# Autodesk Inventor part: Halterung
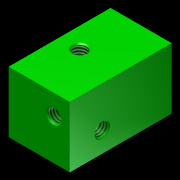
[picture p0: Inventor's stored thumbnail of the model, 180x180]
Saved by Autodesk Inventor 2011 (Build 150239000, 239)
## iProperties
Created: 2012-06
Part Number: Halterung
Document SubType Name: Modeling
Designer: M.Schulte
Density: 1 g/cm^3
Author: M.Schulte
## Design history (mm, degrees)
sketch "Skizze1"
  geometry: L1 (-7.5, -7.5)-(7.5, -7.5); L2 (7.5, -7.5)-(7.5, 7.5); L3 (7.5, 7.5)-(-7.5, 7.5); L4 (-7.5, 7.5)-(-7.5, -7.5); 4 further points
  constraints: 8 end point, 2 midpoint, 2 parallel, 1 horizontal, 1 horizontal alignment, 1 perpendicular, 1 vertical alignment
  dimensions: "d0" = 15 distance of L1.end L2.end; "d1" = 15 distance of L2.end L3.end (= d0); "d4" = 10 vertical distance of L1.end point (3.5, 2.5); "d5" = 4 horizontal distance of L2.end point (3.5, 2.5)
extrude "Extrusion1" new body sketch "Skizze1" distance "d2" = 25; taper "d3" = 0 deg
hole "Hole1" sketch "Skizze1" diameter "d6" = 3.242; stored, may be unused: countersink angle "d10" = 90 deg, drill point angle "d12" = 118 deg; dims "d7" = 15, "d8" = 4, "d9" = 2, "d11" = 18
sketch "Skizze2"
  geometry: 3 further points
  dimensions: "d13" = 12.5 vertical distance of point (0, 0) point (5, -12.5); "d14" = 5 horizontal distance of point (0, 0) point (5, -12.5)
hole "Hole2" sketch "Skizze2" at (5, -12.5) diameter "d15" = 3.242; stored, may be unused: countersink angle "d19" = 90 deg, drill point angle "d21" = 118 deg; dims "d16" = 15, "d17" = 4, "d18" = 2, "d20" = 18
sketch "Skizze3"
  geometry: 3 further points
  dimensions: "d22" = 8 horizontal distance of point (0, 0) point (8, 5); "d23" = 5 vertical distance of point (0, 0) point (8, 5)
hole "Hole3" sketch "Skizze3" at (8, 5) diameter "d24" = 3.242; stored, may be unused: countersink angle "d28" = 90 deg, drill point angle "d30" = 118 deg; dims "d25" = 15, "d26" = 4, "d27" = 2, "d29" = 18
chamfer "Fase1" distance "d31" = 0.3; stored, may be unused: second distance "d32" = 2, angle "d33" = 45 deg
node "Volumenkörper1"
